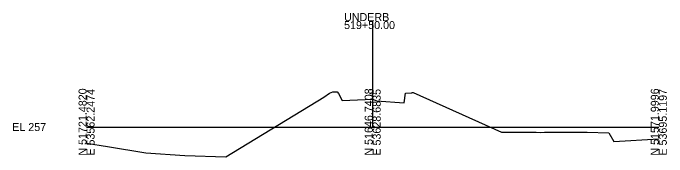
# Model space of a CAD drawing. Extents: x 12366 to 12594, y 96215 to 101752.
# Drawn here: x 12365.6 to 12594.1, y 98214.2 to 98264.5 of the extents above; entities that cross this region are included whole.
import ezdxf

# ---------------------------------------------------------------- set-up
doc = ezdxf.new("R2010")
doc.units = 0
for name, color, linetype in [('Level 10', 7, 'Continuous'), ('Level 60', 7, 'Continuous'), ('Level 63', 7, 'Continuous')]:
    doc.layers.add(name, color=color, linetype=linetype)

msp = doc.modelspace()

# ---------------------------------------------------------------- linework, layer by layer
at = {"layer": 'Level 60'}
for p, q in [((12474.24, 98235.04), (12476.18, 98236.49)), ((12476.18, 98236.49), (12477.36, 98236.96)), ((12477.36, 98236.96), (12478.9, 98237)), ((12478.9, 98237), (12479.4, 98236.41)), ((12479.4, 98236.41), (12480.68, 98233.93)), ((12502.3, 98233.09), (12502.81, 98236.47)), ((12502.81, 98236.47), (12505.04, 98236.59)), ((12505.04, 98236.59), (12505.11, 98236.78)), ((12505.11, 98236.78), (12505.49, 98236.73)), ((12505.49, 98236.73), (12536.3, 98222.79)), ((12440.03, 98214.18), (12474.24, 98235.04)), ((12480.68, 98233.93), (12491.34, 98234.43)), ((12491.34, 98234.43), (12492.68, 98233.78)), ((12492.68, 98233.78), (12502.3, 98233.09)), ((12536.3, 98222.79), (12548.49, 98222.8)), ((12548.49, 98222.8), (12549.84, 98222.78)), ((12549.84, 98222.78), (12551.33, 98222.86)), ((12551.33, 98222.86), (12566.3, 98222.88)), ((12566.3, 98222.88), (12573.82, 98222.63)), ((12573.82, 98222.63), (12575.62, 98219.57)), ((12575.62, 98219.57), (12591.3, 98220.46)), ((12391.3, 98218.95), (12398.58, 98217.83)), ((12398.58, 98217.83), (12412.03, 98215.67)), ((12412.03, 98215.67), (12425.67, 98214.69)), ((12425.67, 98214.69), (12440.03, 98214.18))]:
    msp.add_line(p, q, dxfattribs=at)
at = {"layer": 'Level 63'}
for p, q in [((12491.3, 98224.64), (12491.3, 98261.72)), ((12391.3, 98224.64), (12491.3, 98224.64)), ((12491.3, 98224.64), (12591.3, 98224.64))]:
    msp.add_line(p, q, dxfattribs=at)

# ---------------------------------------------------------------- texts
at = {"layer": 'Level 10'}
msp.add_text('266.79', height=0.6, rotation=90, dxfattribs=at).set_placement((12490.9, 98235.43))
at = {"layer": 'Level 63'}
for s, p in [('UNDERB', (12481.3, 98261.72)), ('519+50.00', (12481.3, 98258.92)), ('EL 257', (12365.3, 98223.24))]:
    msp.add_text(s, height=2.8, dxfattribs=at).set_placement(p)
for s, p in [('N 51721.4820', (12391.3, 98214.64)), ('E 53562.2474', (12394.1, 98214.64)), ('N 51646.7408', (12491.3, 98214.64)), ('E 53628.6835', (12494.1, 98214.64)), ('N 51571.9996', (12591.3, 98214.64)), ('E 53695.1197', (12594.1, 98214.64))]:
    msp.add_text(s, height=2.8, rotation=90, dxfattribs=at).set_placement(p)

doc.saveas('drawing.dxf')
